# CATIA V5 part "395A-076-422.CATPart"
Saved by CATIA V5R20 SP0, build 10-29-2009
Part number: 395A-076-422
Source: Unknown
Property "ARTICLENO": "395A-076-422"
Property "B": "15"
Property "BOMINFO": "395A-076-422"
Property "C": "27.000"
Property "CODE": "395A-076-422"
Property "D": "76.000"
Property "D1": "95.000"
Property "D2": "5x25"
Property "D3": "40"
Property "D5": "60"
Property "D6": "56.000"
Property "H": "8.000"
Property "L": "422.000"
Property "L1": "15.000"
Property "L2": "360.000"
Property "L3": "19.000"
Property "L4": "27"
Property "LINA": "395A-076-422"
Property "M": "36.000"
Property "M1": "20.000"
Property "M2": "27.000"
Property "MAXLOAD": "31500 Kg"
Property "MDW": "63000 Kg"
Property "NB": "395A-076-422"
Property "NBSYN": "$CODE."
Property "NN": "395A"
Property "NT": "Pin"
Property "P": "9"
Property "S": "19.000"
Property "SUPPLIER": "CF"
Bounding box of the stored display mesh (mm): x 0 to 422, y -47.5 to 47.5, z -47.5 to 47.5
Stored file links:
  C:\Users\Utente\Desktop\3D files 395A\395A-076-422.CATPart
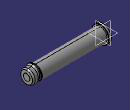
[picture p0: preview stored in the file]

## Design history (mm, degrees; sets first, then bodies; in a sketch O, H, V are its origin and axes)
Body1 "Geometry.1" (main body)
  Solid1 "395A-076-422.catpart": solid without history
